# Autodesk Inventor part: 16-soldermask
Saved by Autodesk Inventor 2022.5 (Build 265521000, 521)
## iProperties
Created: 2024-07
Part Number: 16-soldermask
Material: Generic
Document SubType Name: Modeling
Designer: AdminForWorker
Density: 1 g/cm^3
Appearance: Default
Title: 16-soldermask
Author: AdminForWorker
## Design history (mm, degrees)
feature "Body1"
body "Solid1"
